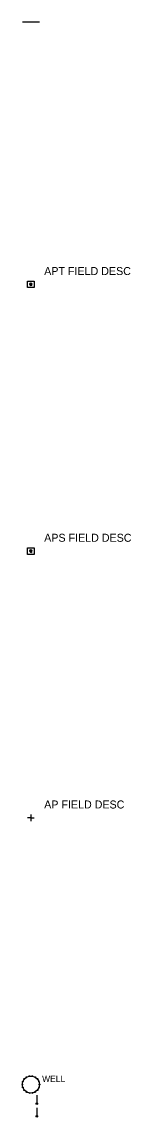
# Model space of a CAD drawing. Extents: x 98 to 2902, y -6 to 903.
# Drawn here: x 98.3 to 118.8, y -6.1 to 199.2 of the extents above; entities that cross this region are included whole.
import ezdxf

# ---------------------------------------------------------------- set-up
doc = ezdxf.new("R2010")
doc.units = 0
for name, color, linetype in [('V-AERI-PNPT', 7, 'Continuous'), ('V-FUEL-DEVC', 7, 'Continuous'), ('V-SITE-STRC', 7, 'Continuous'), ('V-SURV-DATA', 7, 'Continuous')]:
    doc.layers.add(name, color=color, linetype=linetype)

msp = doc.modelspace()

# ---------------------------------------------------------------- linework, layer by layer
at = {"layer": 'V-AERI-PNPT'}
for p, q in [((99.88, 150), (100.12, 150)), ((99.88, 100), (100.12, 100))]:
    msp.add_line(p, q, dxfattribs=at)
for points in [[(99.39, 150.61), (100.61, 150.61), (100.61, 149.39), (99.39, 149.39)], [(99.39, 100.61), (100.61, 100.61), (100.61, 99.39), (99.39, 99.39)]]:
    msp.add_lwpolyline(points, close=True, dxfattribs=at)
for centre, radius, start, end in [((100, 150), 0.231, 91.4818, 90.9603), ((100, 150), 0.115, 95.6476, 94.6084), ((100, 100), 0.231, 91.4818, 90.9603), ((100, 100), 0.115, 95.6476, 94.6084)]:
    msp.add_arc(centre, radius, start, end, dxfattribs=at)
at = {"layer": 'V-FUEL-DEVC'}
for p, q in [((98.39, 0), (98.39, 0)), ((98.48, 0.55), (98.48, 0.55)), ((98.76, 1.04), (98.76, 1.04)), ((99.19, 1.4), (99.19, 1.4)), ((99.72, 1.59), (99.72, 1.59)), ((100.28, 1.59), (100.28, 1.59)), ((100.81, 1.4), (100.81, 1.4)), ((101.24, 1.04), (101.24, 1.04)), ((101.52, 0.55), (101.52, 0.55)), ((101.61, 0), (101.61, 0)), ((98.48, -0.55), (98.48, -0.55)), ((98.76, -1.04), (98.76, -1.04)), ((99.19, -1.4), (99.19, -1.4)), ((99.72, -1.59), (99.72, -1.59)), ((100.28, -1.59), (100.28, -1.59)), ((100.81, -1.4), (100.81, -1.4)), ((101.12, -2.02), (101.12, -3.45)), ((101.24, -1.04), (101.24, -1.04)), ((101.52, -0.55), (101.52, -0.55)), ((101.12, -4.38), (101.12, -5.81))]:
    msp.add_line(p, q, dxfattribs=at)
for centre, radius in [((98.39, 0), 0.0717), ((100, 0), 1.59), ((98.48, 0.55), 0.0717), ((98.76, 1.04), 0.0717), ((99.19, 1.4), 0.0717), ((99.72, 1.59), 0.0717), ((100.28, 1.59), 0.0717), ((100.81, 1.4), 0.0717), ((101.24, 1.04), 0.0717), ((101.52, 0.55), 0.0717), ((101.61, 0), 0.0717), ((98.48, -0.55), 0.0717), ((98.76, -1.04), 0.0717), ((99.19, -1.4), 0.0717), ((99.72, -1.59), 0.0717), ((100.28, -1.59), 0.0717), ((100.81, -1.4), 0.0717), ((101.24, -1.04), 0.0717), ((101.52, -0.55), 0.0717), ((101.12, -3.59), 0.143), ((101.12, -5.96), 0.143)]:
    msp.add_circle(centre, radius, dxfattribs=at)
at = {"layer": 'V-SITE-STRC'}
msp.add_line((98.41, 199.21), (101.59, 199.21), dxfattribs=at)
at = {"layer": 'V-SURV-DATA'}
for p, q in [((100, 50), (99.35, 50)), ((100, 50.65), (100, 49.35)), ((100, 50), (100.65, 50))]:
    msp.add_line(p, q, dxfattribs=at)

# ---------------------------------------------------------------- texts
at = {"layer": 'V-AERI-PNPT'}
for s, p in [('APT FIELD DESC', (102.5, 151.75)), ('APS FIELD DESC', (102.5, 101.75)), ('AP FIELD DESC', (102.5, 51.75))]:
    msp.add_text(s, height=1.5, dxfattribs=at).set_placement(p)
at = {"layer": 'V-FUEL-DEVC'}
msp.add_text('WELL', height=1.189, dxfattribs=at).set_placement((102.11, 0.49))

doc.saveas('drawing.dxf')
